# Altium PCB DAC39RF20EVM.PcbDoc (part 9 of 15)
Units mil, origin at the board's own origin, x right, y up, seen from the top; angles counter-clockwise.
Board outline 6200 x 2716.54 mil, 16 copper layers (Top Layer, L2 GND, L3 PWR, L4 GND, L5 PWR, L6 GND, L7 SIG, L8 GND, L9 GND, L10 SIG, L11 GND, L12 PWR, L13 GND, L14 PWR, L15 GND, Bottom Layer), stack 76.97 mil thick; 766 components, 495 nets, 3414 pads, 2373 vias.
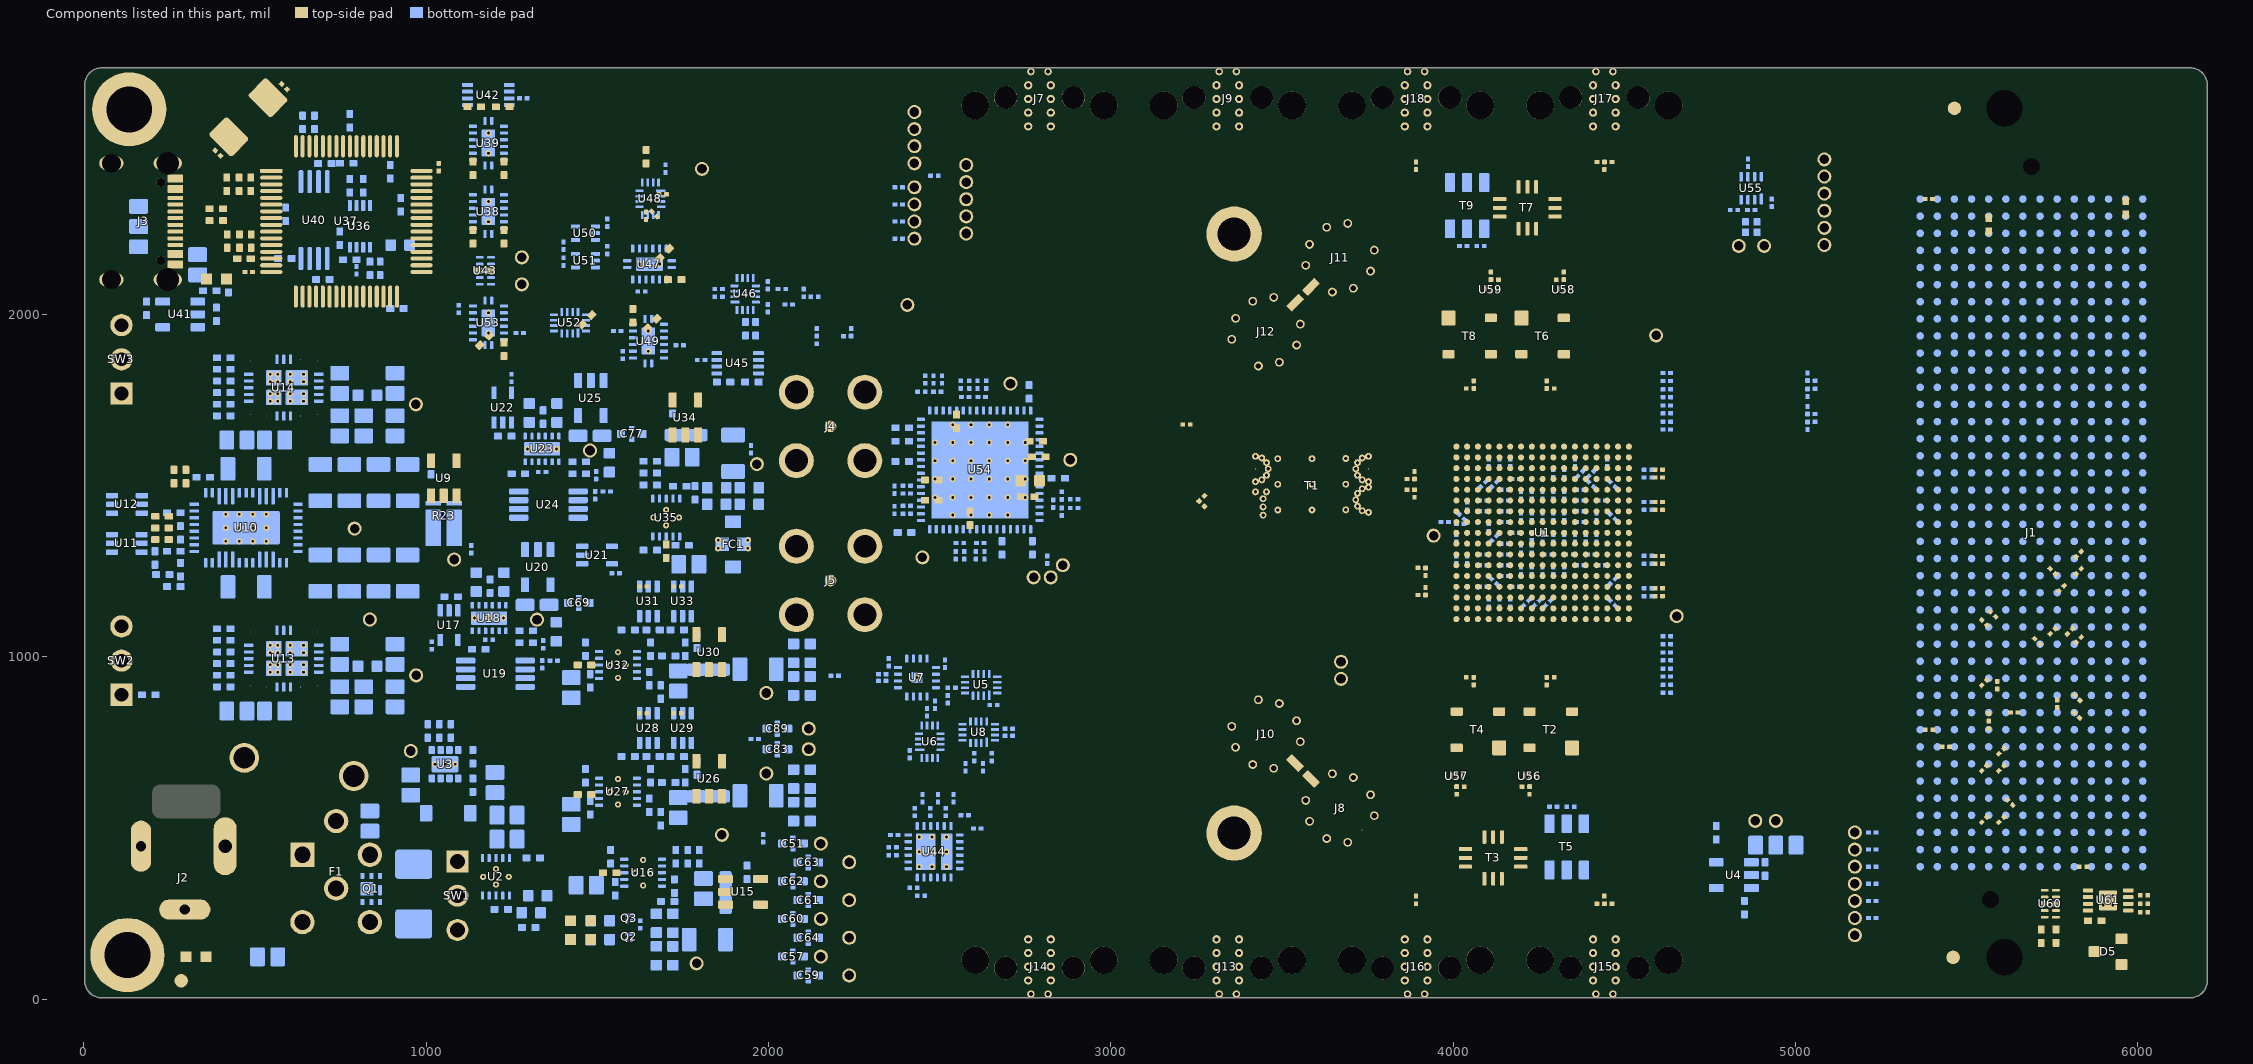
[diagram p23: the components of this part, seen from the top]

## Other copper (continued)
L3 PWR:
  pour cut-out: 3434.48,1511.7 ccw(c3422.48,1511.7) 3422.48,1523.7 ccw(c3422.48,1511.7) 3410.48,1511.7 ccw(c3422.48,1511.7) 3422.48,1499.7 ccw(c3422.48,1511.7)
  pour cut-out: 3452.98,1516.66 ccw(c3440.98,1516.66) 3440.98,1528.66 ccw(c3440.98,1516.66) 3428.98,1516.66 ccw(c3440.98,1516.66) 3440.98,1504.66 ccw(c3440.98,1516.66)
  pour cut-out: 3466.52,1530.2 ccw(c3454.52,1530.2) 3454.52,1542.2 ccw(c3454.52,1530.2) 3442.52,1530.2 ccw(c3454.52,1530.2) 3454.52,1518.2 ccw(c3454.52,1530.2)
  pour cut-out: 3471.48,1548.7 ccw(c3459.48,1548.7) 3459.48,1560.7 ccw(c3459.48,1548.7) 3447.48,1548.7 ccw(c3459.48,1548.7) 3459.48,1536.7 ccw(c3459.48,1548.7)
  pour cut-out: 3466.52,1567.2 ccw(c3454.52,1567.2) 3454.52,1579.2 ccw(c3454.52,1567.2) 3442.52,1567.2 ccw(c3454.52,1567.2) 3454.52,1555.2 ccw(c3454.52,1567.2)
  pour cut-out: 3452.98,1580.74 ccw(c3440.98,1580.74) 3440.98,1592.74 ccw(c3440.98,1580.74) 3428.98,1580.74 ccw(c3440.98,1580.74) 3440.98,1568.74 ccw(c3440.98,1580.74)
  pour cut-out: 3434.48,1585.7 ccw(c3422.48,1585.7) 3422.48,1597.7 ccw(c3422.48,1585.7) 3410.48,1585.7 ccw(c3422.48,1585.7) 3422.48,1573.7 ccw(c3422.48,1585.7)
  pour cut-out: 3740.48,1495.7 ccw(c3752.48,1495.7) 3752.48,1483.7 ccw(c3752.48,1495.7) 3764.48,1495.7 ccw(c3752.48,1495.7) 3752.48,1507.7 ccw(c3752.48,1495.7)
  pour cut-out: 3721.98,1490.74 ccw(c3733.98,1490.74) 3733.98,1478.74 ccw(c3733.98,1490.74) 3745.98,1490.74 ccw(c3733.98,1490.74) 3733.98,1502.74 ccw(c3733.98,1490.74)
  pour cut-out: 3708.43,1477.2 ccw(c3720.43,1477.2) 3720.43,1465.2 ccw(c3720.43,1477.2) 3732.43,1477.2 ccw(c3720.43,1477.2) 3720.43,1489.2 ccw(c3720.43,1477.2)
  pour cut-out: 3703.48,1458.7 ccw(c3715.48,1458.7) 3715.48,1446.7 ccw(c3715.48,1458.7) 3727.48,1458.7 ccw(c3715.48,1458.7) 3715.48,1470.7 ccw(c3715.48,1458.7)
  pour cut-out: 3708.43,1440.2 ccw(c3720.43,1440.2) 3720.43,1428.2 ccw(c3720.43,1440.2) 3732.43,1440.2 ccw(c3720.43,1440.2) 3720.43,1452.2 ccw(c3720.43,1440.2)
  pour cut-out: 3721.98,1426.66 ccw(c3733.98,1426.66) 3733.98,1414.66 ccw(c3733.98,1426.66) 3745.98,1426.66 ccw(c3733.98,1426.66) 3733.98,1438.66 ccw(c3733.98,1426.66)
  pour cut-out: 3740.48,1421.7 ccw(c3752.48,1421.7) 3752.48,1409.7 ccw(c3752.48,1421.7) 3764.48,1421.7 ccw(c3752.48,1421.7) 3752.48,1433.7 ccw(c3752.48,1421.7)
  pour cut-out: 3740.48,1511.7 ccw(c3752.48,1511.7) 3752.48,1499.7 ccw(c3752.48,1511.7) 3764.48,1511.7 ccw(c3752.48,1511.7) 3752.48,1523.7 ccw(c3752.48,1511.7)
  pour cut-out: 3721.98,1516.66 ccw(c3733.98,1516.66) 3733.98,1504.66 ccw(c3733.98,1516.66) 3745.98,1516.66 ccw(c3733.98,1516.66) 3733.98,1528.66 ccw(c3733.98,1516.66)
  pour cut-out: 3708.43,1530.2 ccw(c3720.43,1530.2) 3720.43,1518.2 ccw(c3720.43,1530.2) 3732.43,1530.2 ccw(c3720.43,1530.2) 3720.43,1542.2 ccw(c3720.43,1530.2)
  pour cut-out: 3703.48,1548.7 ccw(c3715.48,1548.7) 3715.48,1536.7 ccw(c3715.48,1548.7) 3727.48,1548.7 ccw(c3715.48,1548.7) 3715.48,1560.7 ccw(c3715.48,1548.7)
  pour cut-out: 3708.43,1567.2 ccw(c3720.43,1567.2) 3720.43,1555.2 ccw(c3720.43,1567.2) 3732.43,1567.2 ccw(c3720.43,1567.2) 3720.43,1579.2 ccw(c3720.43,1567.2)
  pour cut-out: 3721.98,1580.74 ccw(c3733.98,1580.74) 3733.98,1568.74 ccw(c3733.98,1580.74) 3745.98,1580.74 ccw(c3733.98,1580.74) 3733.98,1592.74 ccw(c3733.98,1580.74)
  pour cut-out: 3740.48,1585.7 ccw(c3752.48,1585.7) 3752.48,1573.7 ccw(c3752.48,1585.7) 3764.48,1585.7 ccw(c3752.48,1585.7) 3752.48,1597.7 ccw(c3752.48,1585.7)
  pour cut-out: 4198,1117 ccw(c4198,1110) 4205,1110 ccw(c4198,1110)
  pour cut-out: 4135.01,1117 ccw(c4135.01,1110) 4142.01,1110 ccw(c4135.01,1110)
  pour cut-out: 4072.02,1117 ccw(c4072.02,1110) 4079.02,1110 ccw(c4072.02,1110)
  pour cut-out: 4040.52,1117 ccw(c4040.52,1110) 4047.52,1110 ccw(c4040.52,1110)
  pour cut-out: 4009.03,1211.49 ccw(c4009.03,1204.49) 4016.03,1204.49 ccw(c4009.03,1204.49)
  pour cut-out: 4009.03,1242.98 ccw(c4009.03,1235.98) 4016.03,1235.98 ccw(c4009.03,1235.98)
  pour cut-out: 4009.03,1494.95 ccw(c4009.03,1487.95) 4016.03,1487.95 ccw(c4009.03,1487.95)
  pour cut-out: 4009.03,1526.45 ccw(c4009.03,1519.45) 4016.03,1519.45 ccw(c4009.03,1519.45)
  pour cut-out: 4040.52,1620.94 ccw(c4040.52,1613.94) 4047.52,1613.94 ccw(c4040.52,1613.94)
  pour cut-out: 4072.02,1620.94 ccw(c4072.02,1613.94) 4079.02,1613.94 ccw(c4072.02,1613.94)
  pour cut-out: 4198,1620.94 ccw(c4198,1613.94) 4205,1613.94 ccw(c4198,1613.94)
  pour cut-out: 4135.01,1620.94 ccw(c4135.01,1613.94) 4142.01,1613.94 ccw(c4135.01,1613.94)
  pour cut-out: 3998.03,1456.46 ccw(c4009.03,1456.46) 4009.03,1445.46 ccw(c4009.03,1456.46) 4020.03,1456.46 ccw(c4009.03,1456.46) 4009.03,1467.46 ccw(c4009.03,1456.46)
  pour cut-out: 4029.52,1487.95 ccw(c4040.52,1487.95) 4040.52,1476.95 ccw(c4040.52,1487.95) 4051.52,1487.95 ccw(c4040.52,1487.95) 4040.52,1498.95 ccw(c4040.52,1487.95)
  pour cut-out: 4029.52,1519.45 ccw(c4040.52,1519.45) 4040.52,1508.45 ccw(c4040.52,1519.45) 4051.52,1519.45 ccw(c4040.52,1519.45) 4040.52,1530.45 ccw(c4040.52,1519.45)
  pour cut-out: 3998.03,1550.94 ccw(c4009.03,1550.94) 4009.03,1539.94 ccw(c4009.03,1550.94) 4020.03,1550.94 ccw(c4009.03,1550.94) 4009.03,1561.94 ccw(c4009.03,1550.94)
  pour cut-out: 4218.5,1613.94 ccw(c4229.5,1613.94) 4229.5,1602.94 ccw(c4229.5,1613.94) 4240.5,1613.94 ccw(c4229.5,1613.94) 4229.5,1624.94 ccw(c4229.5,1613.94)
  pour cut-out: 4155.51,1613.94 ccw(c4166.51,1613.94) 4166.51,1602.94 ccw(c4166.51,1613.94) 4177.51,1613.94 ccw(c4166.51,1613.94) 4166.51,1624.94 ccw(c4166.51,1613.94)
  pour cut-out: 4092.52,1613.94 ccw(c4103.52,1613.94) 4103.52,1602.94 ccw(c4103.52,1613.94) 4114.52,1613.94 ccw(c4103.52,1613.94) 4103.52,1624.94 ccw(c4103.52,1613.94)
  pour cut-out: 4218.5,1110 ccw(c4229.5,1110) 4229.5,1099 ccw(c4229.5,1110) 4240.5,1110 ccw(c4229.5,1110) 4229.5,1121 ccw(c4229.5,1110)
  pour cut-out: 4155.51,1110 ccw(c4166.51,1110) 4166.51,1099 ccw(c4166.51,1110) 4177.51,1110 ccw(c4166.51,1110) 4166.51,1121 ccw(c4166.51,1110)
  pour cut-out: 4092.52,1110 ccw(c4103.52,1110) 4103.52,1099 ccw(c4103.52,1110) 4114.52,1110 ccw(c4103.52,1110) 4103.52,1121 ccw(c4103.52,1110)
  pour cut-out: 4408.51,157.8 cw(c4408.51,174.8) 4391.51,174.8 cw(c4408.51,174.8) 4408.51,191.8 cw(c4408.51,174.8) 4425.51,174.8 cw(c4408.51,174.8)
  pour cut-out: 4408.51,117.8 cw(c4408.51,134.8) 4391.51,134.8 cw(c4408.51,134.8) 4408.51,151.8 cw(c4408.51,134.8) 4425.51,134.8 cw(c4408.51,134.8)
  pour cut-out: 4408.51,77.8 cw(c4408.51,94.8) 4391.51,94.8 cw(c4408.51,94.8) 4408.51,111.8 cw(c4408.51,94.8) 4425.51,94.8 cw(c4408.51,94.8)
  pour cut-out: 4408.51,37.8 cw(c4408.51,54.8) 4391.51,54.8 cw(c4408.51,54.8) 4408.51,71.8 cw(c4408.51,54.8) 4425.51,54.8 cw(c4408.51,54.8)
  pour cut-out: 4416.51,-2.2 cw(c4416.51,14.8) 4399.51,14.8 cw(c4416.51,14.8) 4416.51,31.8 cw(c4416.51,14.8) 4433.51,14.8 cw(c4416.51,14.8)
  pour cut-out: 4466.51,-2.2 cw(c4466.51,14.8) 4449.51,14.8 cw(c4466.51,14.8) 4466.51,31.8 cw(c4466.51,14.8) 4483.51,14.8 cw(c4466.51,14.8)
  pour cut-out: 4474.51,37.8 cw(c4474.51,54.8) 4457.51,54.8 cw(c4474.51,54.8) 4474.51,71.8 cw(c4474.51,54.8) 4491.51,54.8 cw(c4474.51,54.8)
  pour cut-out: 4474.51,77.8 cw(c4474.51,94.8) 4457.51,94.8 cw(c4474.51,94.8) 4474.51,111.8 cw(c4474.51,94.8) 4491.51,94.8 cw(c4474.51,94.8)
  pour cut-out: 4474.51,157.8 cw(c4474.51,174.8) 4457.51,174.8 cw(c4474.51,174.8) 4474.51,191.8 cw(c4474.51,174.8) 4491.51,174.8 cw(c4474.51,174.8)
  pour cut-out: 4474.51,117.8 cw(c4474.51,134.8) 4457.51,134.8 cw(c4474.51,134.8) 4474.51,151.8 cw(c4474.51,134.8) 4491.51,134.8 cw(c4474.51,134.8)
  pour cut-out: 3858.51,157.8 cw(c3858.51,174.8) 3841.51,174.8 cw(c3858.51,174.8) 3858.51,191.8 cw(c3858.51,174.8) 3875.51,174.8 cw(c3858.51,174.8)
  pour cut-out: 3858.51,117.8 cw(c3858.51,134.8) 3841.51,134.8 cw(c3858.51,134.8) 3858.51,151.8 cw(c3858.51,134.8) 3875.51,134.8 cw(c3858.51,134.8)
  pour cut-out: 3858.51,77.8 cw(c3858.51,94.8) 3841.51,94.8 cw(c3858.51,94.8) 3858.51,111.8 cw(c3858.51,94.8) 3875.51,94.8 cw(c3858.51,94.8)
  pour cut-out: 3858.51,37.8 cw(c3858.51,54.8) 3841.51,54.8 cw(c3858.51,54.8) 3858.51,71.8 cw(c3858.51,54.8) 3875.51,54.8 cw(c3858.51,54.8)
  pour cut-out: 3866.51,-2.2 cw(c3866.51,14.8) 3849.51,14.8 cw(c3866.51,14.8) 3866.51,31.8 cw(c3866.51,14.8) 3883.51,14.8 cw(c3866.51,14.8)
  pour cut-out: 3916.51,-2.2 cw(c3916.51,14.8) 3899.51,14.8 cw(c3916.51,14.8) 3916.51,31.8 cw(c3916.51,14.8) 3933.51,14.8 cw(c3916.51,14.8)
  pour cut-out: 3924.51,37.8 cw(c3924.51,54.8) 3907.51,54.8 cw(c3924.51,54.8) 3924.51,71.8 cw(c3924.51,54.8) 3941.51,54.8 cw(c3924.51,54.8)
  pour cut-out: 3924.51,77.8 cw(c3924.51,94.8) 3907.51,94.8 cw(c3924.51,94.8) 3924.51,111.8 cw(c3924.51,94.8) 3941.51,94.8 cw(c3924.51,94.8)
  pour cut-out: 3924.51,157.8 cw(c3924.51,174.8) 3907.51,174.8 cw(c3924.51,174.8) 3924.51,191.8 cw(c3924.51,174.8) 3941.51,174.8 cw(c3924.51,174.8)
  pour cut-out: 3924.51,117.8 cw(c3924.51,134.8) 3907.51,134.8 cw(c3924.51,134.8) 3924.51,151.8 cw(c3924.51,134.8) 3941.51,134.8 cw(c3924.51,134.8)
  pour cut-out: 3308.51,157.8 cw(c3308.51,174.8) 3291.51,174.8 cw(c3308.51,174.8) 3308.51,191.8 cw(c3308.51,174.8) 3325.51,174.8 cw(c3308.51,174.8)
  pour cut-out: 3308.51,117.8 cw(c3308.51,134.8) 3291.51,134.8 cw(c3308.51,134.8) 3308.51,151.8 cw(c3308.51,134.8) 3325.51,134.8 cw(c3308.51,134.8)
  pour cut-out: 3308.51,77.8 cw(c3308.51,94.8) 3291.51,94.8 cw(c3308.51,94.8) 3308.51,111.8 cw(c3308.51,94.8) 3325.51,94.8 cw(c3308.51,94.8)
  pour cut-out: 3308.51,37.8 cw(c3308.51,54.8) 3291.51,54.8 cw(c3308.51,54.8) 3308.51,71.8 cw(c3308.51,54.8) 3325.51,54.8 cw(c3308.51,54.8)
  pour cut-out: 3316.51,-2.2 cw(c3316.51,14.8) 3299.51,14.8 cw(c3316.51,14.8) 3316.51,31.8 cw(c3316.51,14.8) 3333.51,14.8 cw(c3316.51,14.8)
  pour cut-out: 3366.51,-2.2 cw(c3366.51,14.8) 3349.51,14.8 cw(c3366.51,14.8) 3366.51,31.8 cw(c3366.51,14.8) 3383.51,14.8 cw(c3366.51,14.8)
  pour cut-out: 3374.51,37.8 cw(c3374.51,54.8) 3357.51,54.8 cw(c3374.51,54.8) 3374.51,71.8 cw(c3374.51,54.8) 3391.51,54.8 cw(c3374.51,54.8)
  pour cut-out: 3374.51,77.8 cw(c3374.51,94.8) 3357.51,94.8 cw(c3374.51,94.8) 3374.51,111.8 cw(c3374.51,94.8) 3391.51,94.8 cw(c3374.51,94.8)
  pour cut-out: 3374.51,157.8 cw(c3374.51,174.8) 3357.51,174.8 cw(c3374.51,174.8) 3374.51,191.8 cw(c3374.51,174.8) 3391.51,174.8 cw(c3374.51,174.8)
  pour cut-out: 3374.51,117.8 cw(c3374.51,134.8) 3357.51,134.8 cw(c3374.51,134.8) 3374.51,151.8 cw(c3374.51,134.8) 3391.51,134.8 cw(c3374.51,134.8)
  pour cut-out: 2758.51,157.8 cw(c2758.51,174.8) 2741.51,174.8 cw(c2758.51,174.8) 2758.51,191.8 cw(c2758.51,174.8) 2775.51,174.8 cw(c2758.51,174.8)
  pour cut-out: 2758.51,117.8 cw(c2758.51,134.8) 2741.51,134.8 cw(c2758.51,134.8) 2758.51,151.8 cw(c2758.51,134.8) 2775.51,134.8 cw(c2758.51,134.8)
  pour cut-out: 2758.51,77.8 cw(c2758.51,94.8) 2741.51,94.8 cw(c2758.51,94.8) 2758.51,111.8 cw(c2758.51,94.8) 2775.51,94.8 cw(c2758.51,94.8)
  pour cut-out: 2758.51,37.8 cw(c2758.51,54.8) 2741.51,54.8 cw(c2758.51,54.8) 2758.51,71.8 cw(c2758.51,54.8) 2775.51,54.8 cw(c2758.51,54.8)
  pour cut-out: 2766.51,-2.2 cw(c2766.51,14.8) 2749.51,14.8 cw(c2766.51,14.8) 2766.51,31.8 cw(c2766.51,14.8) 2783.51,14.8 cw(c2766.51,14.8)
  pour cut-out: 2816.51,-2.2 cw(c2816.51,14.8) 2799.51,14.8 cw(c2816.51,14.8) 2816.51,31.8 cw(c2816.51,14.8) 2833.51,14.8 cw(c2816.51,14.8)
  pour cut-out: 2824.51,37.8 cw(c2824.51,54.8) 2807.51,54.8 cw(c2824.51,54.8) 2824.51,71.8 cw(c2824.51,54.8) 2841.51,54.8 cw(c2824.51,54.8)
  pour cut-out: 2824.51,77.8 cw(c2824.51,94.8) 2807.51,94.8 cw(c2824.51,94.8) 2824.51,111.8 cw(c2824.51,94.8) 2841.51,94.8 cw(c2824.51,94.8)
  pour cut-out: 2824.51,157.8 cw(c2824.51,174.8) 2807.51,174.8 cw(c2824.51,174.8) 2824.51,191.8 cw(c2824.51,174.8) 2841.51,174.8 cw(c2824.51,174.8)
  pour cut-out: 2824.51,117.8 cw(c2824.51,134.8) 2807.51,134.8 cw(c2824.51,134.8) 2824.51,151.8 cw(c2824.51,134.8) 2841.51,134.8 cw(c2824.51,134.8)
  pour cut-out: 2824.51,2566.14 cw(c2824.51,2549.14) 2841.51,2549.14 cw(c2824.51,2549.14) 2824.51,2532.14 cw(c2824.51,2549.14) 2807.51,2549.14 cw(c2824.51,2549.14)
  pour cut-out: 2824.51,2606.14 cw(c2824.51,2589.14) 2841.51,2589.14 cw(c2824.51,2589.14) 2824.51,2572.14 cw(c2824.51,2589.14) 2807.51,2589.14 cw(c2824.51,2589.14)
  pour cut-out: 2824.51,2646.14 cw(c2824.51,2629.14) 2841.51,2629.14 cw(c2824.51,2629.14) 2824.51,2612.14 cw(c2824.51,2629.14) 2807.51,2629.14 cw(c2824.51,2629.14)
  pour cut-out: 2824.51,2686.14 cw(c2824.51,2669.14) 2841.51,2669.14 cw(c2824.51,2669.14) 2824.51,2652.14 cw(c2824.51,2669.14) 2807.51,2669.14 cw(c2824.51,2669.14)
  pour cut-out: 2816.51,2726.14 cw(c2816.51,2709.14) 2833.51,2709.14 cw(c2816.51,2709.14) 2816.51,2692.14 cw(c2816.51,2709.14) 2799.51,2709.14 cw(c2816.51,2709.14)
  pour cut-out: 2766.51,2726.14 cw(c2766.51,2709.14) 2783.51,2709.14 cw(c2766.51,2709.14) 2766.51,2692.14 cw(c2766.51,2709.14) 2749.51,2709.14 cw(c2766.51,2709.14)
  pour cut-out: 2758.51,2686.14 cw(c2758.51,2669.14) 2775.51,2669.14 cw(c2758.51,2669.14) 2758.51,2652.14 cw(c2758.51,2669.14) 2741.51,2669.14 cw(c2758.51,2669.14)
  pour cut-out: 2758.51,2646.14 cw(c2758.51,2629.14) 2775.51,2629.14 cw(c2758.51,2629.14) 2758.51,2612.14 cw(c2758.51,2629.14) 2741.51,2629.14 cw(c2758.51,2629.14)
  pour cut-out: 2758.51,2566.14 cw(c2758.51,2549.14) 2775.51,2549.14 cw(c2758.51,2549.14) 2758.51,2532.14 cw(c2758.51,2549.14) 2741.51,2549.14 cw(c2758.51,2549.14)
  pour cut-out: 2758.51,2606.14 cw(c2758.51,2589.14) 2775.51,2589.14 cw(c2758.51,2589.14) 2758.51,2572.14 cw(c2758.51,2589.14) 2741.51,2589.14 cw(c2758.51,2589.14)
  pour cut-out: 3374.51,2566.14 cw(c3374.51,2549.14) 3391.51,2549.14 cw(c3374.51,2549.14) 3374.51,2532.14 cw(c3374.51,2549.14) 3357.51,2549.14 cw(c3374.51,2549.14)
  pour cut-out: 3374.51,2606.14 cw(c3374.51,2589.14) 3391.51,2589.14 cw(c3374.51,2589.14) 3374.51,2572.14 cw(c3374.51,2589.14) 3357.51,2589.14 cw(c3374.51,2589.14)
  pour cut-out: 3374.51,2646.14 cw(c3374.51,2629.14) 3391.51,2629.14 cw(c3374.51,2629.14) 3374.51,2612.14 cw(c3374.51,2629.14) 3357.51,2629.14 cw(c3374.51,2629.14)
  pour cut-out: 3374.51,2686.14 cw(c3374.51,2669.14) 3391.51,2669.14 cw(c3374.51,2669.14) 3374.51,2652.14 cw(c3374.51,2669.14) 3357.51,2669.14 cw(c3374.51,2669.14)
  pour cut-out: 3366.51,2726.14 cw(c3366.51,2709.14) 3383.51,2709.14 cw(c3366.51,2709.14) 3366.51,2692.14 cw(c3366.51,2709.14) 3349.51,2709.14 cw(c3366.51,2709.14)
  pour cut-out: 3316.51,2726.14 cw(c3316.51,2709.14) 3333.51,2709.14 cw(c3316.51,2709.14) 3316.51,2692.14 cw(c3316.51,2709.14) 3299.51,2709.14 cw(c3316.51,2709.14)
  pour cut-out: 3308.51,2686.14 cw(c3308.51,2669.14) 3325.51,2669.14 cw(c3308.51,2669.14) 3308.51,2652.14 cw(c3308.51,2669.14) 3291.51,2669.14 cw(c3308.51,2669.14)
  pour cut-out: 3308.51,2646.14 cw(c3308.51,2629.14) 3325.51,2629.14 cw(c3308.51,2629.14) 3308.51,2612.14 cw(c3308.51,2629.14) 3291.51,2629.14 cw(c3308.51,2629.14)
  pour cut-out: 3308.51,2566.14 cw(c3308.51,2549.14) 3325.51,2549.14 cw(c3308.51,2549.14) 3308.51,2532.14 cw(c3308.51,2549.14) 3291.51,2549.14 cw(c3308.51,2549.14)
  pour cut-out: 3308.51,2606.14 cw(c3308.51,2589.14) 3325.51,2589.14 cw(c3308.51,2589.14) 3308.51,2572.14 cw(c3308.51,2589.14) 3291.51,2589.14 cw(c3308.51,2589.14)
  pour cut-out: 3924.51,2566.14 cw(c3924.51,2549.14) 3941.51,2549.14 cw(c3924.51,2549.14) 3924.51,2532.14 cw(c3924.51,2549.14) 3907.51,2549.14 cw(c3924.51,2549.14)
  pour cut-out: 3924.51,2606.14 cw(c3924.51,2589.14) 3941.51,2589.14 cw(c3924.51,2589.14) 3924.51,2572.14 cw(c3924.51,2589.14) 3907.51,2589.14 cw(c3924.51,2589.14)
  pour cut-out: 3924.51,2646.14 cw(c3924.51,2629.14) 3941.51,2629.14 cw(c3924.51,2629.14) 3924.51,2612.14 cw(c3924.51,2629.14) 3907.51,2629.14 cw(c3924.51,2629.14)
  pour cut-out: 3924.51,2686.14 cw(c3924.51,2669.14) 3941.51,2669.14 cw(c3924.51,2669.14) 3924.51,2652.14 cw(c3924.51,2669.14) 3907.51,2669.14 cw(c3924.51,2669.14)
  pour cut-out: 3916.51,2726.14 cw(c3916.51,2709.14) 3933.51,2709.14 cw(c3916.51,2709.14) 3916.51,2692.14 cw(c3916.51,2709.14) 3899.51,2709.14 cw(c3916.51,2709.14)
  pour cut-out: 3866.51,2726.14 cw(c3866.51,2709.14) 3883.51,2709.14 cw(c3866.51,2709.14) 3866.51,2692.14 cw(c3866.51,2709.14) 3849.51,2709.14 cw(c3866.51,2709.14)
  pour cut-out: 3858.51,2686.14 cw(c3858.51,2669.14) 3875.51,2669.14 cw(c3858.51,2669.14) 3858.51,2652.14 cw(c3858.51,2669.14) 3841.51,2669.14 cw(c3858.51,2669.14)
  pour cut-out: 3858.51,2646.14 cw(c3858.51,2629.14) 3875.51,2629.14 cw(c3858.51,2629.14) 3858.51,2612.14 cw(c3858.51,2629.14) 3841.51,2629.14 cw(c3858.51,2629.14)
  pour cut-out: 3858.51,2566.14 cw(c3858.51,2549.14) 3875.51,2549.14 cw(c3858.51,2549.14) 3858.51,2532.14 cw(c3858.51,2549.14) 3841.51,2549.14 cw(c3858.51,2549.14)
  pour cut-out: 3858.51,2606.14 cw(c3858.51,2589.14) 3875.51,2589.14 cw(c3858.51,2589.14) 3858.51,2572.14 cw(c3858.51,2589.14) 3841.51,2589.14 cw(c3858.51,2589.14)
  pour cut-out: 4408.51,2606.14 cw(c4408.51,2589.14) 4425.51,2589.14 cw(c4408.51,2589.14) 4408.51,2572.14 cw(c4408.51,2589.14) 4391.51,2589.14 cw(c4408.51,2589.14)
  pour cut-out: 4408.51,2566.14 cw(c4408.51,2549.14) 4425.51,2549.14 cw(c4408.51,2549.14) 4408.51,2532.14 cw(c4408.51,2549.14) 4391.51,2549.14 cw(c4408.51,2549.14)
  pour cut-out: 4408.51,2646.14 cw(c4408.51,2629.14) 4425.51,2629.14 cw(c4408.51,2629.14) 4408.51,2612.14 cw(c4408.51,2629.14) 4391.51,2629.14 cw(c4408.51,2629.14)
  pour cut-out: 4408.51,2686.14 cw(c4408.51,2669.14) 4425.51,2669.14 cw(c4408.51,2669.14) 4408.51,2652.14 cw(c4408.51,2669.14) 4391.51,2669.14 cw(c4408.51,2669.14)
  pour cut-out: 4416.51,2726.14 cw(c4416.51,2709.14) 4433.51,2709.14 cw(c4416.51,2709.14) 4416.51,2692.14 cw(c4416.51,2709.14) 4399.51,2709.14 cw(c4416.51,2709.14)
  pour cut-out: 4466.51,2726.14 cw(c4466.51,2709.14) 4483.51,2709.14 cw(c4466.51,2709.14) 4466.51,2692.14 cw(c4466.51,2709.14) 4449.51,2709.14 cw(c4466.51,2709.14)
  pour cut-out: 4474.51,2686.14 cw(c4474.51,2669.14) 4491.51,2669.14 cw(c4474.51,2669.14) 4474.51,2652.14 cw(c4474.51,2669.14) 4457.51,2669.14 cw(c4474.51,2669.14)
  pour cut-out: 4474.51,2646.14 cw(c4474.51,2629.14) 4491.51,2629.14 cw(c4474.51,2629.14) 4474.51,2612.14 cw(c4474.51,2629.14) 4457.51,2629.14 cw(c4474.51,2629.14)
  pour cut-out: 4474.51,2606.14 cw(c4474.51,2589.14) 4491.51,2589.14 cw(c4474.51,2589.14) 4474.51,2572.14 cw(c4474.51,2589.14) 4457.51,2589.14 cw(c4474.51,2589.14)
  pour cut-out: 4474.51,2566.14 cw(c4474.51,2549.14) 4491.51,2549.14 cw(c4474.51,2549.14) 4474.51,2532.14 cw(c4474.51,2549.14) 4457.51,2549.14 cw(c4474.51,2549.14)
  pour cut-out: 4090,1974.84 4130,1974.84 4130,2004.84 4090,2004.84
  pour cut-out: 4303.02,1974.84 4343.02,1974.84 4343.02,2004.84 4303.02,2004.84
  pour cut-out: 4303.02,1868.94 4343.02,1868.94 4343.02,1898.94 4303.02,1898.94
  pour cut-out: 4090,1868.94 4130,1868.94 4130,1898.94 4090,1898.94
  pour cut-out: 3990,719.09 4030,719.09 4030,749.09 3990,749.09
  pour cut-out: 4203.02,719.09 4243.02,719.09 4243.02,749.09 4203.02,749.09
  pour cut-out: 4203.02,825 4243.02,825 4243.02,855 4203.02,855
  pour cut-out: 3990,825 4030,825 4030,855 3990,855
  pour cut-out: 3776.48,1560.7 3776.48,1536.7 3748.48,1536.7 3741.48,1543.7 3741.48,1553.7 3748.48,1560.7
  pour cut-out: 3776.48,1470.7 3776.48,1446.7 3748.48,1446.7 3741.48,1453.7 3741.48,1463.7 3748.48,1470.7
  pour cut-out: 3402.48,1536.7 3402.48,1560.7 3430.48,1560.7 3437.48,1553.7 3437.48,1543.7 3430.48,1536.7
  text ".Layer_Name" at 577.59,-856.2 h60
L4 GND:
  pour cut-out: 3434.48,1511.7 ccw(c3422.48,1511.7) 3422.48,1523.7 ccw(c3422.48,1511.7) 3410.48,1511.7 ccw(c3422.48,1511.7) 3422.48,1499.7 ccw(c3422.48,1511.7)
  pour cut-out: 3452.98,1516.66 ccw(c3440.98,1516.66) 3440.98,1528.66 ccw(c3440.98,1516.66) 3428.98,1516.66 ccw(c3440.98,1516.66) 3440.98,1504.66 ccw(c3440.98,1516.66)
  pour cut-out: 3466.52,1530.2 ccw(c3454.52,1530.2) 3454.52,1542.2 ccw(c3454.52,1530.2) 3442.52,1530.2 ccw(c3454.52,1530.2) 3454.52,1518.2 ccw(c3454.52,1530.2)
  pour cut-out: 3471.48,1548.7 ccw(c3459.48,1548.7) 3459.48,1560.7 ccw(c3459.48,1548.7) 3447.48,1548.7 ccw(c3459.48,1548.7) 3459.48,1536.7 ccw(c3459.48,1548.7)
  pour cut-out: 3466.52,1567.2 ccw(c3454.52,1567.2) 3454.52,1579.2 ccw(c3454.52,1567.2) 3442.52,1567.2 ccw(c3454.52,1567.2) 3454.52,1555.2 ccw(c3454.52,1567.2)
  pour cut-out: 3452.98,1580.74 ccw(c3440.98,1580.74) 3440.98,1592.74 ccw(c3440.98,1580.74) 3428.98,1580.74 ccw(c3440.98,1580.74) 3440.98,1568.74 ccw(c3440.98,1580.74)
  pour cut-out: 3434.48,1585.7 ccw(c3422.48,1585.7) 3422.48,1597.7 ccw(c3422.48,1585.7) 3410.48,1585.7 ccw(c3422.48,1585.7) 3422.48,1573.7 ccw(c3422.48,1585.7)
  pour cut-out: 3740.48,1495.7 ccw(c3752.48,1495.7) 3752.48,1483.7 ccw(c3752.48,1495.7) 3764.48,1495.7 ccw(c3752.48,1495.7) 3752.48,1507.7 ccw(c3752.48,1495.7)
  pour cut-out: 3721.98,1490.74 ccw(c3733.98,1490.74) 3733.98,1478.74 ccw(c3733.98,1490.74) 3745.98,1490.74 ccw(c3733.98,1490.74) 3733.98,1502.74 ccw(c3733.98,1490.74)
  pour cut-out: 3708.43,1477.2 ccw(c3720.43,1477.2) 3720.43,1465.2 ccw(c3720.43,1477.2) 3732.43,1477.2 ccw(c3720.43,1477.2) 3720.43,1489.2 ccw(c3720.43,1477.2)
  pour cut-out: 3703.48,1458.7 ccw(c3715.48,1458.7) 3715.48,1446.7 ccw(c3715.48,1458.7) 3727.48,1458.7 ccw(c3715.48,1458.7) 3715.48,1470.7 ccw(c3715.48,1458.7)
  pour cut-out: 3708.43,1440.2 ccw(c3720.43,1440.2) 3720.43,1428.2 ccw(c3720.43,1440.2) 3732.43,1440.2 ccw(c3720.43,1440.2) 3720.43,1452.2 ccw(c3720.43,1440.2)
  pour cut-out: 3721.98,1426.66 ccw(c3733.98,1426.66) 3733.98,1414.66 ccw(c3733.98,1426.66) 3745.98,1426.66 ccw(c3733.98,1426.66) 3733.98,1438.66 ccw(c3733.98,1426.66)
  pour cut-out: 3740.48,1421.7 ccw(c3752.48,1421.7) 3752.48,1409.7 ccw(c3752.48,1421.7) 3764.48,1421.7 ccw(c3752.48,1421.7) 3752.48,1433.7 ccw(c3752.48,1421.7)
  pour cut-out: 3740.48,1511.7 ccw(c3752.48,1511.7) 3752.48,1499.7 ccw(c3752.48,1511.7) 3764.48,1511.7 ccw(c3752.48,1511.7) 3752.48,1523.7 ccw(c3752.48,1511.7)
  pour cut-out: 3721.98,1516.66 ccw(c3733.98,1516.66) 3733.98,1504.66 ccw(c3733.98,1516.66) 3745.98,1516.66 ccw(c3733.98,1516.66) 3733.98,1528.66 ccw(c3733.98,1516.66)
  pour cut-out: 3708.43,1530.2 ccw(c3720.43,1530.2) 3720.43,1518.2 ccw(c3720.43,1530.2) 3732.43,1530.2 ccw(c3720.43,1530.2) 3720.43,1542.2 ccw(c3720.43,1530.2)
  pour cut-out: 3703.48,1548.7 ccw(c3715.48,1548.7) 3715.48,1536.7 ccw(c3715.48,1548.7) 3727.48,1548.7 ccw(c3715.48,1548.7) 3715.48,1560.7 ccw(c3715.48,1548.7)
  pour cut-out: 3708.43,1567.2 ccw(c3720.43,1567.2) 3720.43,1555.2 ccw(c3720.43,1567.2) 3732.43,1567.2 ccw(c3720.43,1567.2) 3720.43,1579.2 ccw(c3720.43,1567.2)
  pour cut-out: 3721.98,1580.74 ccw(c3733.98,1580.74) 3733.98,1568.74 ccw(c3733.98,1580.74) 3745.98,1580.74 ccw(c3733.98,1580.74) 3733.98,1592.74 ccw(c3733.98,1580.74)
  pour cut-out: 3740.48,1585.7 ccw(c3752.48,1585.7) 3752.48,1573.7 ccw(c3752.48,1585.7) 3764.48,1585.7 ccw(c3752.48,1585.7) 3752.48,1597.7 ccw(c3752.48,1585.7)
  pour cut-out: 3998.03,1456.46 ccw(c4009.03,1456.46) 4009.03,1445.46 ccw(c4009.03,1456.46) 4020.03,1456.46 ccw(c4009.03,1456.46) 4009.03,1467.46 ccw(c4009.03,1456.46)
  pour cut-out: 4029.52,1487.95 ccw(c4040.52,1487.95) 4040.52,1476.95 ccw(c4040.52,1487.95) 4051.52,1487.95 ccw(c4040.52,1487.95) 4040.52,1498.95 ccw(c4040.52,1487.95)
  pour cut-out: 4029.52,1519.45 ccw(c4040.52,1519.45) 4040.52,1508.45 ccw(c4040.52,1519.45) 4051.52,1519.45 ccw(c4040.52,1519.45) 4040.52,1530.45 ccw(c4040.52,1519.45)
  pour cut-out: 3998.03,1550.94 ccw(c4009.03,1550.94) 4009.03,1539.94 ccw(c4009.03,1550.94) 4020.03,1550.94 ccw(c4009.03,1550.94) 4009.03,1561.94 ccw(c4009.03,1550.94)
  pour cut-out: 4218.5,1613.94 ccw(c4229.5,1613.94) 4229.5,1602.94 ccw(c4229.5,1613.94) 4240.5,1613.94 ccw(c4229.5,1613.94) 4229.5,1624.94 ccw(c4229.5,1613.94)
  pour cut-out: 4155.51,1613.94 ccw(c4166.51,1613.94) 4166.51,1602.94 ccw(c4166.51,1613.94) 4177.51,1613.94 ccw(c4166.51,1613.94) 4166.51,1624.94 ccw(c4166.51,1613.94)
  pour cut-out: 4092.52,1613.94 ccw(c4103.52,1613.94) 4103.52,1602.94 ccw(c4103.52,1613.94) 4114.52,1613.94 ccw(c4103.52,1613.94) 4103.52,1624.94 ccw(c4103.52,1613.94)
  pour cut-out: 4218.5,1110 ccw(c4229.5,1110) 4229.5,1099 ccw(c4229.5,1110) 4240.5,1110 ccw(c4229.5,1110) 4229.5,1121 ccw(c4229.5,1110)
  pour cut-out: 4155.51,1110 ccw(c4166.51,1110) 4166.51,1099 ccw(c4166.51,1110) 4177.51,1110 ccw(c4166.51,1110) 4166.51,1121 ccw(c4166.51,1110)
  pour cut-out: 4092.52,1110 ccw(c4103.52,1110) 4103.52,1099 ccw(c4103.52,1110) 4114.52,1110 ccw(c4103.52,1110) 4103.52,1121 ccw(c4103.52,1110)
  pour cut-out: 4408.51,157.8 cw(c4408.51,174.8) 4391.51,174.8 cw(c4408.51,174.8) 4408.51,191.8 cw(c4408.51,174.8) 4425.51,174.8 cw(c4408.51,174.8)
  pour cut-out: 4408.51,117.8 cw(c4408.51,134.8) 4391.51,134.8 cw(c4408.51,134.8) 4408.51,151.8 cw(c4408.51,134.8) 4425.51,134.8 cw(c4408.51,134.8)
  pour cut-out: 4408.51,77.8 cw(c4408.51,94.8) 4391.51,94.8 cw(c4408.51,94.8) 4408.51,111.8 cw(c4408.51,94.8) 4425.51,94.8 cw(c4408.51,94.8)
  pour cut-out: 4408.51,37.8 cw(c4408.51,54.8) 4391.51,54.8 cw(c4408.51,54.8) 4408.51,71.8 cw(c4408.51,54.8) 4425.51,54.8 cw(c4408.51,54.8)
  pour cut-out: 4416.51,-2.2 cw(c4416.51,14.8) 4399.51,14.8 cw(c4416.51,14.8) 4416.51,31.8 cw(c4416.51,14.8) 4433.51,14.8 cw(c4416.51,14.8)
  pour cut-out: 4466.51,-2.2 cw(c4466.51,14.8) 4449.51,14.8 cw(c4466.51,14.8) 4466.51,31.8 cw(c4466.51,14.8) 4483.51,14.8 cw(c4466.51,14.8)
  pour cut-out: 4474.51,37.8 cw(c4474.51,54.8) 4457.51,54.8 cw(c4474.51,54.8) 4474.51,71.8 cw(c4474.51,54.8) 4491.51,54.8 cw(c4474.51,54.8)
  pour cut-out: 4474.51,77.8 cw(c4474.51,94.8) 4457.51,94.8 cw(c4474.51,94.8) 4474.51,111.8 cw(c4474.51,94.8) 4491.51,94.8 cw(c4474.51,94.8)
  pour cut-out: 4474.51,157.8 cw(c4474.51,174.8) 4457.51,174.8 cw(c4474.51,174.8) 4474.51,191.8 cw(c4474.51,174.8) 4491.51,174.8 cw(c4474.51,174.8)
  pour cut-out: 4474.51,117.8 cw(c4474.51,134.8) 4457.51,134.8 cw(c4474.51,134.8) 4474.51,151.8 cw(c4474.51,134.8) 4491.51,134.8 cw(c4474.51,134.8)
  pour cut-out: 3858.51,157.8 cw(c3858.51,174.8) 3841.51,174.8 cw(c3858.51,174.8) 3858.51,191.8 cw(c3858.51,174.8) 3875.51,174.8 cw(c3858.51,174.8)
  pour cut-out: 3858.51,117.8 cw(c3858.51,134.8) 3841.51,134.8 cw(c3858.51,134.8) 3858.51,151.8 cw(c3858.51,134.8) 3875.51,134.8 cw(c3858.51,134.8)
  pour cut-out: 3858.51,77.8 cw(c3858.51,94.8) 3841.51,94.8 cw(c3858.51,94.8) 3858.51,111.8 cw(c3858.51,94.8) 3875.51,94.8 cw(c3858.51,94.8)
  pour cut-out: 3858.51,37.8 cw(c3858.51,54.8) 3841.51,54.8 cw(c3858.51,54.8) 3858.51,71.8 cw(c3858.51,54.8) 3875.51,54.8 cw(c3858.51,54.8)
  pour cut-out: 3866.51,-2.2 cw(c3866.51,14.8) 3849.51,14.8 cw(c3866.51,14.8) 3866.51,31.8 cw(c3866.51,14.8) 3883.51,14.8 cw(c3866.51,14.8)
  pour cut-out: 3916.51,-2.2 cw(c3916.51,14.8) 3899.51,14.8 cw(c3916.51,14.8) 3916.51,31.8 cw(c3916.51,14.8) 3933.51,14.8 cw(c3916.51,14.8)
  pour cut-out: 3924.51,37.8 cw(c3924.51,54.8) 3907.51,54.8 cw(c3924.51,54.8) 3924.51,71.8 cw(c3924.51,54.8) 3941.51,54.8 cw(c3924.51,54.8)
  pour cut-out: 3924.51,77.8 cw(c3924.51,94.8) 3907.51,94.8 cw(c3924.51,94.8) 3924.51,111.8 cw(c3924.51,94.8) 3941.51,94.8 cw(c3924.51,94.8)
  pour cut-out: 3924.51,157.8 cw(c3924.51,174.8) 3907.51,174.8 cw(c3924.51,174.8) 3924.51,191.8 cw(c3924.51,174.8) 3941.51,174.8 cw(c3924.51,174.8)
  pour cut-out: 3924.51,117.8 cw(c3924.51,134.8) 3907.51,134.8 cw(c3924.51,134.8) 3924.51,151.8 cw(c3924.51,134.8) 3941.51,134.8 cw(c3924.51,134.8)
  pour cut-out: 3308.51,157.8 cw(c3308.51,174.8) 3291.51,174.8 cw(c3308.51,174.8) 3308.51,191.8 cw(c3308.51,174.8) 3325.51,174.8 cw(c3308.51,174.8)
  pour cut-out: 3308.51,117.8 cw(c3308.51,134.8) 3291.51,134.8 cw(c3308.51,134.8) 3308.51,151.8 cw(c3308.51,134.8) 3325.51,134.8 cw(c3308.51,134.8)
  pour cut-out: 3308.51,77.8 cw(c3308.51,94.8) 3291.51,94.8 cw(c3308.51,94.8) 3308.51,111.8 cw(c3308.51,94.8) 3325.51,94.8 cw(c3308.51,94.8)
  pour cut-out: 3308.51,37.8 cw(c3308.51,54.8) 3291.51,54.8 cw(c3308.51,54.8) 3308.51,71.8 cw(c3308.51,54.8) 3325.51,54.8 cw(c3308.51,54.8)
  pour cut-out: 3316.51,-2.2 cw(c3316.51,14.8) 3299.51,14.8 cw(c3316.51,14.8) 3316.51,31.8 cw(c3316.51,14.8) 3333.51,14.8 cw(c3316.51,14.8)
  pour cut-out: 3366.51,-2.2 cw(c3366.51,14.8) 3349.51,14.8 cw(c3366.51,14.8) 3366.51,31.8 cw(c3366.51,14.8) 3383.51,14.8 cw(c3366.51,14.8)
  pour cut-out: 3374.51,37.8 cw(c3374.51,54.8) 3357.51,54.8 cw(c3374.51,54.8) 3374.51,71.8 cw(c3374.51,54.8) 3391.51,54.8 cw(c3374.51,54.8)
  pour cut-out: 3374.51,77.8 cw(c3374.51,94.8) 3357.51,94.8 cw(c3374.51,94.8) 3374.51,111.8 cw(c3374.51,94.8) 3391.51,94.8 cw(c3374.51,94.8)
  pour cut-out: 3374.51,157.8 cw(c3374.51,174.8) 3357.51,174.8 cw(c3374.51,174.8) 3374.51,191.8 cw(c3374.51,174.8) 3391.51,174.8 cw(c3374.51,174.8)
  pour cut-out: 3374.51,117.8 cw(c3374.51,134.8) 3357.51,134.8 cw(c3374.51,134.8) 3374.51,151.8 cw(c3374.51,134.8) 3391.51,134.8 cw(c3374.51,134.8)
  pour cut-out: 2758.51,157.8 cw(c2758.51,174.8) 2741.51,174.8 cw(c2758.51,174.8) 2758.51,191.8 cw(c2758.51,174.8) 2775.51,174.8 cw(c2758.51,174.8)
  pour cut-out: 2758.51,117.8 cw(c2758.51,134.8) 2741.51,134.8 cw(c2758.51,134.8) 2758.51,151.8 cw(c2758.51,134.8) 2775.51,134.8 cw(c2758.51,134.8)
  pour cut-out: 2758.51,77.8 cw(c2758.51,94.8) 2741.51,94.8 cw(c2758.51,94.8) 2758.51,111.8 cw(c2758.51,94.8) 2775.51,94.8 cw(c2758.51,94.8)
  pour cut-out: 2758.51,37.8 cw(c2758.51,54.8) 2741.51,54.8 cw(c2758.51,54.8) 2758.51,71.8 cw(c2758.51,54.8) 2775.51,54.8 cw(c2758.51,54.8)
  pour cut-out: 2766.51,-2.2 cw(c2766.51,14.8) 2749.51,14.8 cw(c2766.51,14.8) 2766.51,31.8 cw(c2766.51,14.8) 2783.51,14.8 cw(c2766.51,14.8)
  pour cut-out: 2816.51,-2.2 cw(c2816.51,14.8) 2799.51,14.8 cw(c2816.51,14.8) 2816.51,31.8 cw(c2816.51,14.8) 2833.51,14.8 cw(c2816.51,14.8)
  pour cut-out: 2824.51,37.8 cw(c2824.51,54.8) 2807.51,54.8 cw(c2824.51,54.8) 2824.51,71.8 cw(c2824.51,54.8) 2841.51,54.8 cw(c2824.51,54.8)
  pour cut-out: 2824.51,77.8 cw(c2824.51,94.8) 2807.51,94.8 cw(c2824.51,94.8) 2824.51,111.8 cw(c2824.51,94.8) 2841.51,94.8 cw(c2824.51,94.8)
  pour cut-out: 2824.51,157.8 cw(c2824.51,174.8) 2807.51,174.8 cw(c2824.51,174.8) 2824.51,191.8 cw(c2824.51,174.8) 2841.51,174.8 cw(c2824.51,174.8)
  pour cut-out: 2824.51,117.8 cw(c2824.51,134.8) 2807.51,134.8 cw(c2824.51,134.8) 2824.51,151.8 cw(c2824.51,134.8) 2841.51,134.8 cw(c2824.51,134.8)
  pour cut-out: 2824.51,2566.14 cw(c2824.51,2549.14) 2841.51,2549.14 cw(c2824.51,2549.14) 2824.51,2532.14 cw(c2824.51,2549.14) 2807.51,2549.14 cw(c2824.51,2549.14)
  pour cut-out: 2824.51,2606.14 cw(c2824.51,2589.14) 2841.51,2589.14 cw(c2824.51,2589.14) 2824.51,2572.14 cw(c2824.51,2589.14) 2807.51,2589.14 cw(c2824.51,2589.14)
  pour cut-out: 2824.51,2646.14 cw(c2824.51,2629.14) 2841.51,2629.14 cw(c2824.51,2629.14) 2824.51,2612.14 cw(c2824.51,2629.14) 2807.51,2629.14 cw(c2824.51,2629.14)
  pour cut-out: 2824.51,2686.14 cw(c2824.51,2669.14) 2841.51,2669.14 cw(c2824.51,2669.14) 2824.51,2652.14 cw(c2824.51,2669.14) 2807.51,2669.14 cw(c2824.51,2669.14)
  pour cut-out: 2816.51,2726.14 cw(c2816.51,2709.14) 2833.51,2709.14 cw(c2816.51,2709.14) 2816.51,2692.14 cw(c2816.51,2709.14) 2799.51,2709.14 cw(c2816.51,2709.14)
  pour cut-out: 2766.51,2726.14 cw(c2766.51,2709.14) 2783.51,2709.14 cw(c2766.51,2709.14) 2766.51,2692.14 cw(c2766.51,2709.14) 2749.51,2709.14 cw(c2766.51,2709.14)
  pour cut-out: 2758.51,2686.14 cw(c2758.51,2669.14) 2775.51,2669.14 cw(c2758.51,2669.14) 2758.51,2652.14 cw(c2758.51,2669.14) 2741.51,2669.14 cw(c2758.51,2669.14)
  pour cut-out: 2758.51,2646.14 cw(c2758.51,2629.14) 2775.51,2629.14 cw(c2758.51,2629.14) 2758.51,2612.14 cw(c2758.51,2629.14) 2741.51,2629.14 cw(c2758.51,2629.14)
  pour cut-out: 2758.51,2566.14 cw(c2758.51,2549.14) 2775.51,2549.14 cw(c2758.51,2549.14) 2758.51,2532.14 cw(c2758.51,2549.14) 2741.51,2549.14 cw(c2758.51,2549.14)
  pour cut-out: 2758.51,2606.14 cw(c2758.51,2589.14) 2775.51,2589.14 cw(c2758.51,2589.14) 2758.51,2572.14 cw(c2758.51,2589.14) 2741.51,2589.14 cw(c2758.51,2589.14)
  pour cut-out: 3374.51,2566.14 cw(c3374.51,2549.14) 3391.51,2549.14 cw(c3374.51,2549.14) 3374.51,2532.14 cw(c3374.51,2549.14) 3357.51,2549.14 cw(c3374.51,2549.14)
  pour cut-out: 3374.51,2606.14 cw(c3374.51,2589.14) 3391.51,2589.14 cw(c3374.51,2589.14) 3374.51,2572.14 cw(c3374.51,2589.14) 3357.51,2589.14 cw(c3374.51,2589.14)
  pour cut-out: 3374.51,2646.14 cw(c3374.51,2629.14) 3391.51,2629.14 cw(c3374.51,2629.14) 3374.51,2612.14 cw(c3374.51,2629.14) 3357.51,2629.14 cw(c3374.51,2629.14)
  pour cut-out: 3374.51,2686.14 cw(c3374.51,2669.14) 3391.51,2669.14 cw(c3374.51,2669.14) 3374.51,2652.14 cw(c3374.51,2669.14) 3357.51,2669.14 cw(c3374.51,2669.14)
  pour cut-out: 3366.51,2726.14 cw(c3366.51,2709.14) 3383.51,2709.14 cw(c3366.51,2709.14) 3366.51,2692.14 cw(c3366.51,2709.14) 3349.51,2709.14 cw(c3366.51,2709.14)
  pour cut-out: 3316.51,2726.14 cw(c3316.51,2709.14) 3333.51,2709.14 cw(c3316.51,2709.14) 3316.51,2692.14 cw(c3316.51,2709.14) 3299.51,2709.14 cw(c3316.51,2709.14)
  pour cut-out: 3308.51,2686.14 cw(c3308.51,2669.14) 3325.51,2669.14 cw(c3308.51,2669.14) 3308.51,2652.14 cw(c3308.51,2669.14) 3291.51,2669.14 cw(c3308.51,2669.14)
  pour cut-out: 3308.51,2646.14 cw(c3308.51,2629.14) 3325.51,2629.14 cw(c3308.51,2629.14) 3308.51,2612.14 cw(c3308.51,2629.14) 3291.51,2629.14 cw(c3308.51,2629.14)
  pour cut-out: 3308.51,2566.14 cw(c3308.51,2549.14) 3325.51,2549.14 cw(c3308.51,2549.14) 3308.51,2532.14 cw(c3308.51,2549.14) 3291.51,2549.14 cw(c3308.51,2549.14)
  pour cut-out: 3308.51,2606.14 cw(c3308.51,2589.14) 3325.51,2589.14 cw(c3308.51,2589.14) 3308.51,2572.14 cw(c3308.51,2589.14) 3291.51,2589.14 cw(c3308.51,2589.14)
  pour cut-out: 3924.51,2566.14 cw(c3924.51,2549.14) 3941.51,2549.14 cw(c3924.51,2549.14) 3924.51,2532.14 cw(c3924.51,2549.14) 3907.51,2549.14 cw(c3924.51,2549.14)
  pour cut-out: 3924.51,2606.14 cw(c3924.51,2589.14) 3941.51,2589.14 cw(c3924.51,2589.14) 3924.51,2572.14 cw(c3924.51,2589.14) 3907.51,2589.14 cw(c3924.51,2589.14)
  pour cut-out: 3924.51,2646.14 cw(c3924.51,2629.14) 3941.51,2629.14 cw(c3924.51,2629.14) 3924.51,2612.14 cw(c3924.51,2629.14) 3907.51,2629.14 cw(c3924.51,2629.14)
  pour cut-out: 3924.51,2686.14 cw(c3924.51,2669.14) 3941.51,2669.14 cw(c3924.51,2669.14) 3924.51,2652.14 cw(c3924.51,2669.14) 3907.51,2669.14 cw(c3924.51,2669.14)
  pour cut-out: 3916.51,2726.14 cw(c3916.51,2709.14) 3933.51,2709.14 cw(c3916.51,2709.14) 3916.51,2692.14 cw(c3916.51,2709.14) 3899.51,2709.14 cw(c3916.51,2709.14)
  pour cut-out: 3866.51,2726.14 cw(c3866.51,2709.14) 3883.51,2709.14 cw(c3866.51,2709.14) 3866.51,2692.14 cw(c3866.51,2709.14) 3849.51,2709.14 cw(c3866.51,2709.14)
  pour cut-out: 3858.51,2686.14 cw(c3858.51,2669.14) 3875.51,2669.14 cw(c3858.51,2669.14) 3858.51,2652.14 cw(c3858.51,2669.14) 3841.51,2669.14 cw(c3858.51,2669.14)
  pour cut-out: 3858.51,2646.14 cw(c3858.51,2629.14) 3875.51,2629.14 cw(c3858.51,2629.14) 3858.51,2612.14 cw(c3858.51,2629.14) 3841.51,2629.14 cw(c3858.51,2629.14)
  pour cut-out: 3858.51,2566.14 cw(c3858.51,2549.14) 3875.51,2549.14 cw(c3858.51,2549.14) 3858.51,2532.14 cw(c3858.51,2549.14) 3841.51,2549.14 cw(c3858.51,2549.14)
  pour cut-out: 3858.51,2606.14 cw(c3858.51,2589.14) 3875.51,2589.14 cw(c3858.51,2589.14) 3858.51,2572.14 cw(c3858.51,2589.14) 3841.51,2589.14 cw(c3858.51,2589.14)
  pour cut-out: 4408.51,2606.14 cw(c4408.51,2589.14) 4425.51,2589.14 cw(c4408.51,2589.14) 4408.51,2572.14 cw(c4408.51,2589.14) 4391.51,2589.14 cw(c4408.51,2589.14)
  pour cut-out: 4408.51,2566.14 cw(c4408.51,2549.14) 4425.51,2549.14 cw(c4408.51,2549.14) 4408.51,2532.14 cw(c4408.51,2549.14) 4391.51,2549.14 cw(c4408.51,2549.14)
  pour cut-out: 4408.51,2646.14 cw(c4408.51,2629.14) 4425.51,2629.14 cw(c4408.51,2629.14) 4408.51,2612.14 cw(c4408.51,2629.14) 4391.51,2629.14 cw(c4408.51,2629.14)
  pour cut-out: 4408.51,2686.14 cw(c4408.51,2669.14) 4425.51,2669.14 cw(c4408.51,2669.14) 4408.51,2652.14 cw(c4408.51,2669.14) 4391.51,2669.14 cw(c4408.51,2669.14)
  pour cut-out: 4416.51,2726.14 cw(c4416.51,2709.14) 4433.51,2709.14 cw(c4416.51,2709.14) 4416.51,2692.14 cw(c4416.51,2709.14) 4399.51,2709.14 cw(c4416.51,2709.14)
  pour cut-out: 4466.51,2726.14 cw(c4466.51,2709.14) 4483.51,2709.14 cw(c4466.51,2709.14) 4466.51,2692.14 cw(c4466.51,2709.14) 4449.51,2709.14 cw(c4466.51,2709.14)
  pour cut-out: 4474.51,2686.14 cw(c4474.51,2669.14) 4491.51,2669.14 cw(c4474.51,2669.14) 4474.51,2652.14 cw(c4474.51,2669.14) 4457.51,2669.14 cw(c4474.51,2669.14)
  pour cut-out: 4474.51,2646.14 cw(c4474.51,2629.14) 4491.51,2629.14 cw(c4474.51,2629.14) 4474.51,2612.14 cw(c4474.51,2629.14) 4457.51,2629.14 cw(c4474.51,2629.14)
  pour cut-out: 4474.51,2606.14 cw(c4474.51,2589.14) 4491.51,2589.14 cw(c4474.51,2589.14) 4474.51,2572.14 cw(c4474.51,2589.14) 4457.51,2589.14 cw(c4474.51,2589.14)
  pour cut-out: 4474.51,2566.14 cw(c4474.51,2549.14) 4491.51,2549.14 cw(c4474.51,2549.14) 4474.51,2532.14 cw(c4474.51,2549.14) 4457.51,2549.14 cw(c4474.51,2549.14)
  pour cut-out: 4090,1974.84 4130,1974.84 4130,2004.84 4090,2004.84
  pour cut-out: 4303.02,1974.84 4343.02,1974.84 4343.02,2004.84 4303.02,2004.84
  pour cut-out: 4303.02,1868.94 4343.02,1868.94 4343.02,1898.94 4303.02,1898.94
  pour cut-out: 4090,1868.94 4130,1868.94 4130,1898.94 4090,1898.94
  pour cut-out: 3990,719.09 4030,719.09 4030,749.09 3990,749.09
  pour cut-out: 4203.02,719.09 4243.02,719.09 4243.02,749.09 4203.02,749.09
  pour cut-out: 4203.02,825 4243.02,825 4243.02,855 4203.02,855
  pour cut-out: 3990,825 4030,825 4030,855 3990,855
  text ".Layer_Name" at 577.59,-856.2 h60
